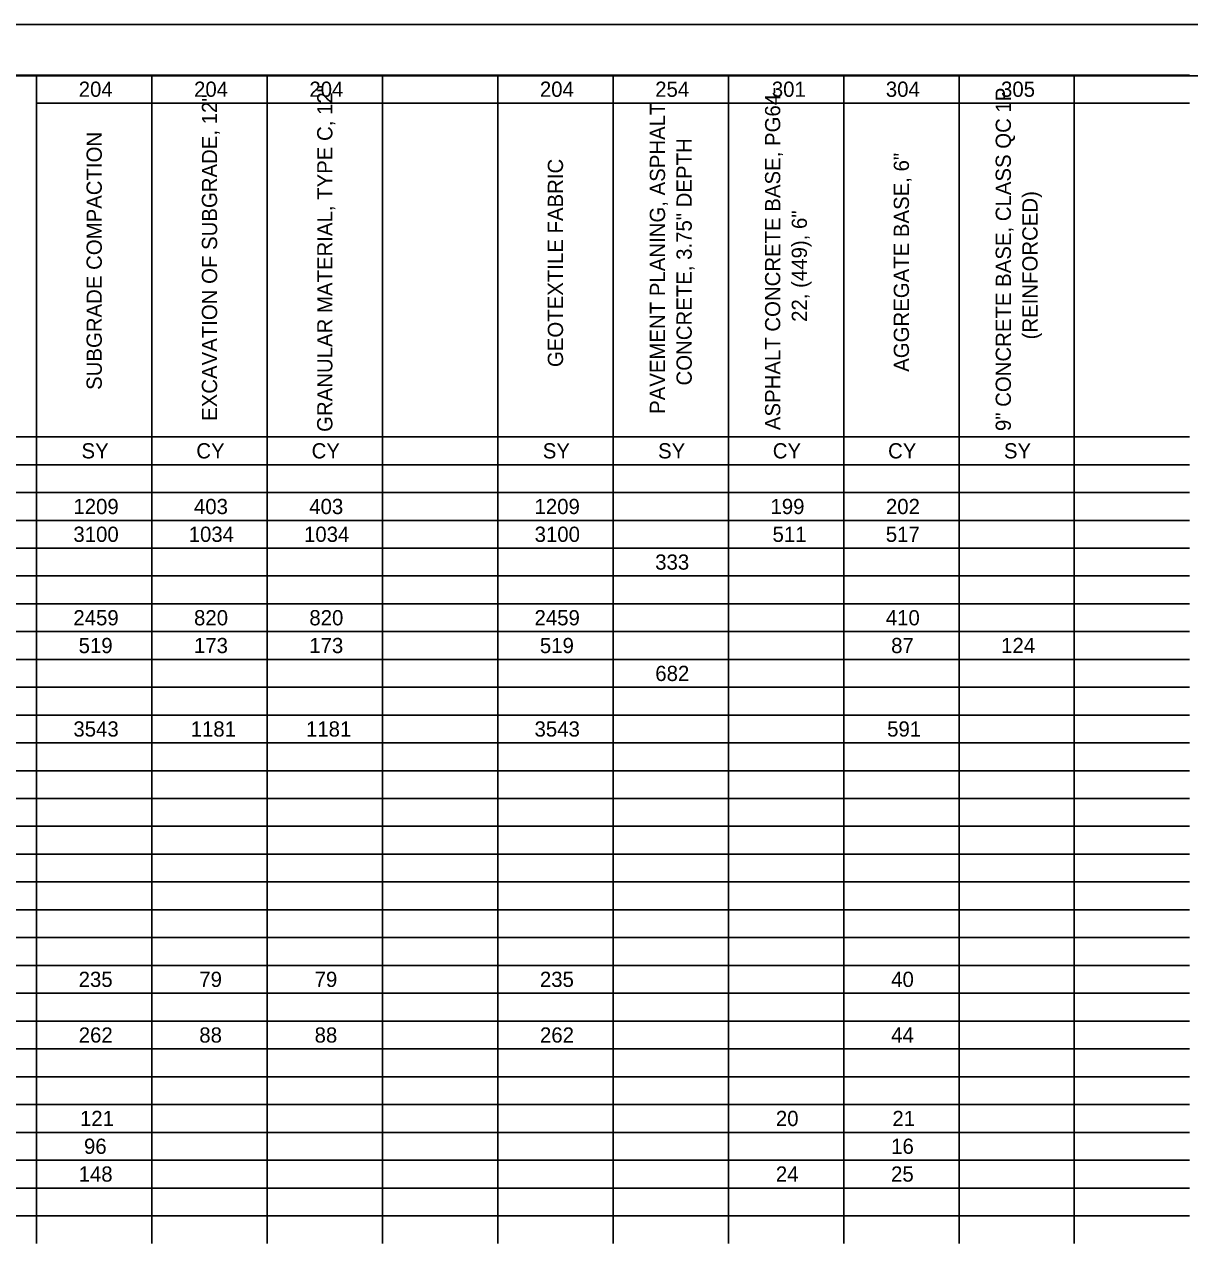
# Model space of a CAD drawing. Extents: x 0 to 34, y 0 to 22.
# Drawn here: x 11.72 to 23.04, y 10.15 to 22 of the extents above; entities that cross this region are included whole.
import ezdxf

# ---------------------------------------------------------------- set-up
doc = ezdxf.new("R2010")
doc.units = 0
for name, color, linetype in [('SH_Border', 7, 'Continuous'), ('SH_Cut_Line', 7, 'Continuous'), ('SH_Text', 7, 'Continuous')]:
    doc.layers.add(name, color=color, linetype=linetype)

msp = doc.modelspace()

# ---------------------------------------------------------------- linework, layer by layer
at = {"layer": 'SH_Border'}
msp.add_lwpolyline([(1.5, 21.5), (33.5, 21.5), (33.5, 0.5), (1.5, 0.5)], close=True, dxfattribs=at)
at = {"layer": 'SH_Cut_Line'}
msp.add_lwpolyline([(0, 0), (34, 0), (34, 22), (0, 22)], close=True, dxfattribs=at)
at = {"layer": 'SH_Text'}
for p, q in [((10.722, 21.505), (11.841, 21.505)), ((11.841, 21.505), (12.961, 21.505)), ((11.841, 21.505), (11.841, 21.235)), ((12.961, 21.505), (14.081, 21.505)), ((12.961, 21.505), (12.961, 21.235)), ((14.081, 21.505), (16.321, 21.505)), ((14.081, 21.505), (14.081, 21.235)), ((15.201, 21.505), (15.201, 21.235)), ((16.321, 21.505), (23.041, 21.505)), ((16.321, 21.505), (16.321, 21.235)), ((17.441, 21.505), (17.441, 21.235)), ((18.561, 21.505), (18.561, 21.235)), ((19.681, 21.505), (19.681, 21.235)), ((20.801, 21.505), (20.801, 21.235)), ((21.921, 21.505), (21.921, 21.235)), ((11.841, 21.235), (12.961, 21.235)), ((11.841, 21.235), (11.841, 20.965)), ((12.961, 21.235), (14.081, 21.235)), ((12.961, 21.235), (12.961, 20.965)), ((14.081, 21.235), (16.321, 21.235)), ((14.081, 21.235), (14.081, 20.965)), ((15.201, 21.235), (15.201, 20.965)), ((16.321, 21.235), (23.041, 21.235)), ((16.321, 21.235), (16.321, 20.965)), ((17.441, 21.235), (17.441, 20.965)), ((18.561, 21.235), (18.561, 20.965)), ((19.681, 21.235), (19.681, 20.965)), ((20.801, 21.235), (20.801, 20.965)), ((21.921, 21.235), (21.921, 20.965)), ((11.841, 20.965), (11.841, 20.694)), ((12.961, 20.965), (12.961, 20.694)), ((14.081, 20.965), (14.081, 20.694)), ((15.201, 20.965), (15.201, 20.694)), ((16.321, 20.965), (16.321, 20.694)), ((17.441, 20.965), (17.441, 20.694)), ((18.561, 20.965), (18.561, 20.694)), ((19.681, 20.965), (19.681, 20.694)), ((20.801, 20.965), (20.801, 20.694)), ((21.921, 20.965), (21.921, 20.694)), ((11.841, 20.694), (11.841, 20.154)), ((12.961, 20.694), (12.961, 20.154)), ((14.081, 20.694), (14.081, 20.154)), ((15.201, 20.694), (15.201, 20.154)), ((16.321, 20.694), (16.321, 20.154)), ((17.441, 20.694), (17.441, 20.154)), ((18.561, 20.694), (18.561, 20.154)), ((19.681, 20.694), (19.681, 20.154)), ((20.801, 20.694), (20.801, 20.154)), ((21.921, 20.694), (21.921, 20.154)), ((11.841, 20.154), (11.841, 19.883)), ((12.961, 20.154), (12.961, 19.883)), ((14.081, 20.154), (14.081, 19.883)), ((15.201, 20.154), (15.201, 19.883)), ((16.321, 20.154), (16.321, 19.883)), ((17.441, 20.154), (17.441, 19.883)), ((18.561, 20.154), (18.561, 19.883)), ((19.681, 20.154), (19.681, 19.883)), ((20.801, 20.154), (20.801, 19.883)), ((21.921, 20.154), (21.921, 19.883)), ((11.841, 19.883), (11.841, 19.613)), ((12.961, 19.883), (12.961, 19.613)), ((14.081, 19.883), (14.081, 19.613)), ((15.201, 19.883), (15.201, 19.613)), ((16.321, 19.883), (16.321, 19.613)), ((17.441, 19.883), (17.441, 19.613)), ((18.561, 19.883), (18.561, 19.613)), ((19.681, 19.883), (19.681, 19.613)), ((20.801, 19.883), (20.801, 19.613)), ((21.921, 19.883), (21.921, 19.613)), ((11.841, 19.613), (11.841, 19.343)), ((12.961, 19.613), (12.961, 19.343)), ((14.081, 19.613), (14.081, 19.343)), ((15.201, 19.613), (15.201, 19.343)), ((16.321, 19.613), (16.321, 19.343)), ((17.441, 19.613), (17.441, 19.343)), ((18.561, 19.613), (18.561, 19.343)), ((19.681, 19.613), (19.681, 19.343)), ((20.801, 19.613), (20.801, 19.343)), ((21.921, 19.613), (21.921, 19.343)), ((11.841, 19.343), (11.841, 19.072)), ((12.961, 19.343), (12.961, 19.072)), ((14.081, 19.343), (14.081, 19.072)), ((15.201, 19.343), (15.201, 19.072)), ((16.321, 19.343), (16.321, 19.072)), ((17.441, 19.343), (17.441, 19.072)), ((18.561, 19.343), (18.561, 19.072)), ((19.681, 19.343), (19.681, 19.072)), ((20.801, 19.343), (20.801, 19.072)), ((21.921, 19.343), (21.921, 19.072)), ((11.841, 19.072), (11.841, 18.802)), ((12.961, 19.072), (12.961, 18.802)), ((14.081, 19.072), (14.081, 18.802)), ((15.201, 19.072), (15.201, 18.802)), ((16.321, 19.072), (16.321, 18.802)), ((17.441, 19.072), (17.441, 18.802)), ((18.561, 19.072), (18.561, 18.802)), ((19.681, 19.072), (19.681, 18.802)), ((20.801, 19.072), (20.801, 18.802)), ((21.921, 19.072), (21.921, 18.802)), ((11.841, 18.802), (11.841, 18.532)), ((12.961, 18.802), (12.961, 18.532)), ((14.081, 18.802), (14.081, 18.532)), ((15.201, 18.802), (15.201, 18.532)), ((16.321, 18.802), (16.321, 18.532)), ((17.441, 18.802), (17.441, 18.532)), ((18.561, 18.802), (18.561, 18.532)), ((19.681, 18.802), (19.681, 18.532)), ((20.801, 18.802), (20.801, 18.532)), ((21.921, 18.802), (21.921, 18.532)), ((11.841, 18.532), (11.841, 18.262)), ((12.961, 18.532), (12.961, 18.262)), ((14.081, 18.532), (14.081, 18.262)), ((15.201, 18.532), (15.201, 18.262)), ((16.321, 18.532), (16.321, 18.262)), ((17.441, 18.532), (17.441, 18.262)), ((18.561, 18.532), (18.561, 18.262)), ((19.681, 18.532), (19.681, 18.262)), ((20.801, 18.532), (20.801, 18.262)), ((21.921, 18.532), (21.921, 18.262)), ((11.841, 18.262), (11.841, 17.991)), ((12.961, 18.262), (12.961, 17.991)), ((14.081, 18.262), (14.081, 17.991)), ((15.201, 18.262), (15.201, 17.991)), ((16.321, 18.262), (16.321, 17.991)), ((17.441, 18.262), (17.441, 17.991)), ((18.561, 18.262), (18.561, 17.991)), ((19.681, 18.262), (19.681, 17.991)), ((20.801, 18.262), (20.801, 17.991)), ((21.921, 18.262), (21.921, 17.991)), ((10.722, 17.991), (11.841, 17.991)), ((11.841, 17.991), (12.961, 17.991)), ((11.841, 17.991), (11.841, 17.721)), ((12.961, 17.991), (14.081, 17.991)), ((12.961, 17.991), (12.961, 17.721)), ((14.081, 17.991), (16.321, 17.991)), ((14.081, 17.991), (14.081, 17.721)), ((15.201, 17.991), (15.201, 17.721)), ((16.321, 17.991), (23.041, 17.991)), ((16.321, 17.991), (16.321, 17.721)), ((17.441, 17.991), (17.441, 17.721)), ((18.561, 17.991), (18.561, 17.721)), ((19.681, 17.991), (19.681, 17.721)), ((20.801, 17.991), (20.801, 17.721)), ((21.921, 17.991), (21.921, 17.721)), ((10.722, 17.721), (11.841, 17.721)), ((11.841, 17.721), (12.961, 17.721)), ((11.841, 17.721), (11.841, 17.451)), ((12.961, 17.721), (14.081, 17.721)), ((12.961, 17.721), (12.961, 17.451)), ((14.081, 17.721), (16.321, 17.721)), ((14.081, 17.721), (14.081, 17.451)), ((15.201, 17.721), (15.201, 17.451)), ((16.321, 17.721), (23.041, 17.721)), ((16.321, 17.721), (16.321, 17.451)), ((17.441, 17.721), (17.441, 17.451)), ((18.561, 17.721), (18.561, 17.451)), ((19.681, 17.721), (19.681, 17.451)), ((20.801, 17.721), (20.801, 17.451)), ((21.921, 17.721), (21.921, 17.451)), ((10.722, 17.451), (11.841, 17.451)), ((11.841, 17.451), (12.961, 17.451)), ((11.841, 17.451), (11.841, 17.18)), ((12.961, 17.451), (14.081, 17.451)), ((12.961, 17.451), (12.961, 17.18)), ((14.081, 17.451), (16.321, 17.451)), ((14.081, 17.451), (14.081, 17.18)), ((15.201, 17.451), (15.201, 17.18)), ((16.321, 17.451), (23.041, 17.451)), ((16.321, 17.451), (16.321, 17.18)), ((17.441, 17.451), (17.441, 17.18)), ((18.561, 17.451), (18.561, 17.18)), ((19.681, 17.451), (19.681, 17.18)), ((20.801, 17.451), (20.801, 17.18)), ((21.921, 17.451), (21.921, 17.18)), ((10.722, 17.18), (11.841, 17.18)), ((11.841, 17.18), (12.961, 17.18)), ((11.841, 17.18), (11.841, 16.91)), ((12.961, 17.18), (14.081, 17.18)), ((12.961, 17.18), (12.961, 16.91)), ((14.081, 17.18), (16.321, 17.18)), ((14.081, 17.18), (14.081, 16.91)), ((15.201, 17.18), (15.201, 16.91)), ((16.321, 17.18), (23.041, 17.18)), ((16.321, 17.18), (16.321, 16.91)), ((17.441, 17.18), (17.441, 16.91)), ((18.561, 17.18), (18.561, 16.91)), ((19.681, 17.18), (19.681, 16.91)), ((20.801, 17.18), (20.801, 16.91)), ((21.921, 17.18), (21.921, 16.91)), ((10.722, 16.91), (11.841, 16.91)), ((11.841, 16.91), (12.961, 16.91)), ((11.841, 16.91), (11.841, 16.369)), ((12.961, 16.91), (14.081, 16.91)), ((12.961, 16.91), (12.961, 16.369)), ((14.081, 16.91), (16.321, 16.91)), ((14.081, 16.91), (14.081, 16.369)), ((15.201, 16.91), (15.201, 16.369)), ((16.321, 16.91), (23.041, 16.91)), ((16.321, 16.91), (16.321, 16.369)), ((17.441, 16.91), (17.441, 16.369)), ((18.561, 16.91), (18.561, 16.369)), ((19.681, 16.91), (19.681, 16.369)), ((20.801, 16.91), (20.801, 16.369)), ((21.921, 16.91), (21.921, 16.369)), ((10.722, 16.64), (11.841, 16.64)), ((11.841, 16.64), (12.961, 16.64)), ((12.961, 16.64), (14.081, 16.64)), ((14.081, 16.64), (16.321, 16.64)), ((16.321, 16.64), (23.041, 16.64)), ((10.722, 16.369), (11.841, 16.369)), ((11.841, 16.369), (12.961, 16.369)), ((11.841, 16.369), (11.841, 16.099)), ((12.961, 16.369), (14.081, 16.369)), ((12.961, 16.369), (12.961, 16.099)), ((14.081, 16.369), (16.321, 16.369)), ((14.081, 16.369), (14.081, 16.099)), ((15.201, 16.369), (15.201, 16.099)), ((16.321, 16.369), (23.041, 16.369)), ((16.321, 16.369), (16.321, 16.099)), ((17.441, 16.369), (17.441, 16.099)), ((18.561, 16.369), (18.561, 16.099)), ((19.681, 16.369), (19.681, 16.099)), ((20.801, 16.369), (20.801, 16.099)), ((21.921, 16.369), (21.921, 16.099)), ((10.722, 16.099), (11.841, 16.099)), ((11.841, 16.099), (12.961, 16.099)), ((11.841, 16.099), (11.841, 15.829)), ((12.961, 16.099), (14.081, 16.099)), ((12.961, 16.099), (12.961, 15.829)), ((14.081, 16.099), (16.321, 16.099)), ((14.081, 16.099), (14.081, 15.829)), ((15.201, 16.099), (15.201, 15.829)), ((16.321, 16.099), (23.041, 16.099)), ((16.321, 16.099), (16.321, 15.829)), ((17.441, 16.099), (17.441, 15.829)), ((18.561, 16.099), (18.561, 15.829)), ((19.681, 16.099), (19.681, 15.829)), ((20.801, 16.099), (20.801, 15.829)), ((21.921, 16.099), (21.921, 15.829)), ((10.722, 15.829), (11.841, 15.829)), ((11.841, 15.829), (12.961, 15.829)), ((11.841, 15.829), (11.841, 15.558)), ((12.961, 15.829), (14.081, 15.829)), ((12.961, 15.829), (12.961, 15.558)), ((14.081, 15.829), (16.321, 15.829)), ((14.081, 15.829), (14.081, 15.558)), ((15.201, 15.829), (15.201, 15.558)), ((16.321, 15.829), (23.041, 15.829)), ((16.321, 15.829), (16.321, 15.558)), ((17.441, 15.829), (17.441, 15.558)), ((18.561, 15.829), (18.561, 15.558)), ((19.681, 15.829), (19.681, 15.558)), ((20.801, 15.829), (20.801, 15.558)), ((21.921, 15.829), (21.921, 15.558)), ((10.722, 15.558), (11.841, 15.558)), ((11.841, 15.558), (12.961, 15.558)), ((11.841, 15.558), (11.841, 15.018)), ((12.961, 15.558), (14.081, 15.558)), ((12.961, 15.558), (12.961, 15.018)), ((14.081, 15.558), (16.321, 15.558)), ((14.081, 15.558), (14.081, 15.018)), ((15.201, 15.558), (15.201, 15.018)), ((16.321, 15.558), (23.041, 15.558)), ((16.321, 15.558), (16.321, 15.018)), ((17.441, 15.558), (17.441, 15.018)), ((18.561, 15.558), (18.561, 15.018)), ((19.681, 15.558), (19.681, 15.018)), ((20.801, 15.558), (20.801, 15.018)), ((21.921, 15.558), (21.921, 15.018)), ((10.722, 15.288), (11.841, 15.288)), ((11.841, 15.288), (12.961, 15.288)), ((12.961, 15.288), (14.081, 15.288)), ((14.081, 15.288), (16.321, 15.288)), ((16.321, 15.288), (23.041, 15.288)), ((10.722, 15.018), (11.841, 15.018)), ((11.841, 15.018), (12.961, 15.018)), ((11.841, 15.018), (11.841, 14.747)), ((12.961, 15.018), (14.081, 15.018)), ((12.961, 15.018), (12.961, 14.747)), ((14.081, 15.018), (16.321, 15.018)), ((14.081, 15.018), (14.081, 14.747)), ((15.201, 15.018), (15.201, 14.747)), ((16.321, 15.018), (23.041, 15.018)), ((16.321, 15.018), (16.321, 14.747)), ((17.441, 15.018), (17.441, 14.747)), ((18.561, 15.018), (18.561, 14.747)), ((19.681, 15.018), (19.681, 14.747)), ((20.801, 15.018), (20.801, 14.747)), ((21.921, 15.018), (21.921, 14.747)), ((10.722, 14.747), (11.841, 14.747)), ((11.841, 14.747), (12.961, 14.747)), ((11.841, 14.747), (11.841, 14.477)), ((12.961, 14.747), (14.081, 14.747)), ((12.961, 14.747), (12.961, 14.477)), ((14.081, 14.747), (16.321, 14.747)), ((14.081, 14.747), (14.081, 14.477)), ((15.201, 14.747), (15.201, 14.477)), ((16.321, 14.747), (23.041, 14.747)), ((16.321, 14.747), (16.321, 14.477)), ((17.441, 14.747), (17.441, 14.477)), ((18.561, 14.747), (18.561, 14.477)), ((19.681, 14.747), (19.681, 14.477)), ((20.801, 14.747), (20.801, 14.477)), ((21.921, 14.747), (21.921, 14.477)), ((10.722, 14.477), (11.841, 14.477)), ((11.841, 14.477), (12.961, 14.477)), ((11.841, 14.477), (11.841, 14.207)), ((12.961, 14.477), (14.081, 14.477)), ((12.961, 14.477), (12.961, 14.207)), ((14.081, 14.477), (16.321, 14.477)), ((14.081, 14.477), (14.081, 14.207)), ((15.201, 14.477), (15.201, 14.207)), ((16.321, 14.477), (23.041, 14.477)), ((16.321, 14.477), (16.321, 14.207)), ((17.441, 14.477), (17.441, 14.207)), ((18.561, 14.477), (18.561, 14.207)), ((19.681, 14.477), (19.681, 14.207)), ((20.801, 14.477), (20.801, 14.207)), ((21.921, 14.477), (21.921, 14.207)), ((10.722, 14.207), (11.841, 14.207)), ((11.841, 14.207), (12.961, 14.207)), ((11.841, 14.207), (11.841, 13.396)), ((12.961, 14.207), (14.081, 14.207)), ((12.961, 14.207), (12.961, 13.396)), ((14.081, 14.207), (16.321, 14.207)), ((14.081, 14.207), (14.081, 13.396)), ((15.201, 14.207), (15.201, 13.396)), ((16.321, 14.207), (23.041, 14.207)), ((16.321, 14.207), (16.321, 13.396)), ((17.441, 14.207), (17.441, 13.396)), ((18.561, 14.207), (18.561, 13.396)), ((19.681, 14.207), (19.681, 13.396)), ((20.801, 14.207), (20.801, 13.396)), ((21.921, 14.207), (21.921, 13.396)), ((10.722, 13.936), (11.841, 13.936)), ((11.841, 13.936), (12.961, 13.936)), ((12.961, 13.936), (14.081, 13.936)), ((14.081, 13.936), (16.321, 13.936)), ((16.321, 13.936), (23.041, 13.936)), ((10.722, 13.666), (11.841, 13.666)), ((11.841, 13.666), (12.961, 13.666)), ((12.961, 13.666), (14.081, 13.666)), ((14.081, 13.666), (16.321, 13.666)), ((16.321, 13.666), (23.041, 13.666)), ((10.722, 13.396), (11.841, 13.396)), ((11.841, 13.396), (12.961, 13.396)), ((11.841, 13.396), (11.841, 13.125)), ((12.961, 13.396), (14.081, 13.396)), ((12.961, 13.396), (12.961, 13.125)), ((14.081, 13.396), (16.321, 13.396)), ((14.081, 13.396), (14.081, 13.125)), ((15.201, 13.396), (15.201, 13.125)), ((16.321, 13.396), (23.041, 13.396)), ((16.321, 13.396), (16.321, 13.125)), ((17.441, 13.396), (17.441, 13.125)), ((18.561, 13.396), (18.561, 13.125)), ((19.681, 13.396), (19.681, 13.125)), ((20.801, 13.396), (20.801, 13.125)), ((21.921, 13.396), (21.921, 13.125)), ((10.722, 13.125), (11.841, 13.125)), ((11.841, 13.125), (12.961, 13.125)), ((11.841, 13.125), (11.841, 12.044)), ((12.961, 13.125), (14.081, 13.125)), ((12.961, 13.125), (12.961, 12.044)), ((14.081, 13.125), (16.321, 13.125)), ((14.081, 13.125), (14.081, 12.044)), ((15.201, 13.125), (15.201, 12.044)), ((16.321, 13.125), (23.041, 13.125)), ((16.321, 13.125), (16.321, 12.044)), ((17.441, 13.125), (17.441, 12.044)), ((18.561, 13.125), (18.561, 12.044)), ((19.681, 13.125), (19.681, 12.044)), ((20.801, 13.125), (20.801, 12.044)), ((21.921, 13.125), (21.921, 12.044)), ((10.722, 12.855), (11.841, 12.855)), ((11.841, 12.855), (12.961, 12.855)), ((12.961, 12.855), (14.081, 12.855)), ((14.081, 12.855), (16.321, 12.855)), ((16.321, 12.855), (23.041, 12.855)), ((10.722, 12.585), (11.841, 12.585)), ((11.841, 12.585), (12.961, 12.585)), ((12.961, 12.585), (14.081, 12.585)), ((14.081, 12.585), (16.321, 12.585)), ((16.321, 12.585), (23.041, 12.585)), ((10.722, 12.314), (11.841, 12.314)), ((11.841, 12.314), (12.961, 12.314)), ((12.961, 12.314), (14.081, 12.314)), ((14.081, 12.314), (16.321, 12.314)), ((16.321, 12.314), (23.041, 12.314)), ((10.722, 12.044), (11.841, 12.044)), ((11.841, 12.044), (12.961, 12.044)), ((11.841, 12.044), (11.841, 11.774)), ((12.961, 12.044), (14.081, 12.044)), ((12.961, 12.044), (12.961, 11.774)), ((14.081, 12.044), (16.321, 12.044)), ((14.081, 12.044), (14.081, 11.774)), ((15.201, 12.044), (15.201, 11.774)), ((16.321, 12.044), (23.041, 12.044)), ((16.321, 12.044), (16.321, 11.774)), ((17.441, 12.044), (17.441, 11.774)), ((18.561, 12.044), (18.561, 11.774)), ((19.681, 12.044), (19.681, 11.774)), ((20.801, 12.044), (20.801, 11.774)), ((21.921, 12.044), (21.921, 11.774)), ((10.722, 11.774), (11.841, 11.774)), ((11.841, 11.774), (12.961, 11.774)), ((11.841, 11.774), (11.841, 10.692)), ((12.961, 11.774), (14.081, 11.774)), ((12.961, 11.774), (12.961, 10.692)), ((14.081, 11.774), (16.321, 11.774)), ((14.081, 11.774), (14.081, 10.692)), ((15.201, 11.774), (15.201, 10.692)), ((16.321, 11.774), (23.041, 11.774)), ((16.321, 11.774), (16.321, 10.692)), ((17.441, 11.774), (17.441, 10.692)), ((18.561, 11.774), (18.561, 10.692)), ((19.681, 11.774), (19.681, 10.692)), ((20.801, 11.774), (20.801, 10.692)), ((21.921, 11.774), (21.921, 10.692)), ((10.722, 11.503), (11.841, 11.503)), ((11.841, 11.503), (12.961, 11.503)), ((12.961, 11.503), (14.081, 11.503)), ((14.081, 11.503), (16.321, 11.503)), ((16.321, 11.503), (23.041, 11.503)), ((10.722, 11.233), (11.841, 11.233)), ((11.841, 11.233), (12.961, 11.233)), ((12.961, 11.233), (14.081, 11.233)), ((14.081, 11.233), (16.321, 11.233)), ((16.321, 11.233), (23.041, 11.233)), ((10.722, 10.963), (11.841, 10.963)), ((11.841, 10.963), (12.961, 10.963)), ((12.961, 10.963), (14.081, 10.963)), ((14.081, 10.963), (16.321, 10.963)), ((16.321, 10.963), (23.041, 10.963)), ((10.722, 10.692), (11.841, 10.692)), ((11.841, 10.692), (12.961, 10.692)), ((11.841, 10.692), (11.841, 10.152)), ((12.961, 10.692), (14.081, 10.692)), ((12.961, 10.692), (12.961, 10.152)), ((14.081, 10.692), (16.321, 10.692)), ((14.081, 10.692), (14.081, 10.152)), ((15.201, 10.692), (15.201, 10.152)), ((16.321, 10.692), (23.041, 10.692)), ((16.321, 10.692), (16.321, 10.152)), ((17.441, 10.692), (17.441, 10.152)), ((18.561, 10.692), (18.561, 10.152)), ((19.681, 10.692), (19.681, 10.152)), ((20.801, 10.692), (20.801, 10.152)), ((21.921, 10.692), (21.921, 10.152)), ((10.722, 10.422), (11.841, 10.422)), ((11.841, 10.422), (12.961, 10.422)), ((12.961, 10.422), (14.081, 10.422)), ((14.081, 10.422), (16.321, 10.422)), ((16.321, 10.422), (23.041, 10.422))]:
    msp.add_line(p, q, dxfattribs=at)

# ---------------------------------------------------------------- texts
for s, p in [('204', (12.251, 21.296)), ('204', (13.371, 21.296)), ('204', (14.491, 21.296)), ('204', (16.73, 21.296)), ('254', (17.85, 21.296)), ('301', (18.983, 21.296)), ('304', (20.09, 21.296)), ('305', (21.209, 21.296)), ('SY', (12.278, 17.782)), ('CY', (13.393, 17.782)), ('CY', (14.513, 17.782)), ('SY', (16.758, 17.782)), ('SY', (17.878, 17.782)), ('CY', (18.992, 17.782)), ('CY', (20.112, 17.782)), ('SY', (21.237, 17.782)), ('1209', (12.199, 17.241)), ('403', (13.37, 17.241)), ('403', (14.49, 17.241)), ('1209', (16.678, 17.241)), ('199', (18.97, 17.241)), ('202', (20.091, 17.241)), ('3100', (12.199, 16.971)), ('1034', (13.319, 16.971)), ('1034', (14.439, 16.971)), ('3100', (16.679, 16.971)), ('511', (18.99, 16.971)), ('517', (20.09, 16.971)), ('333', (17.85, 16.701)), ('2459', (12.199, 16.16)), ('820', (13.371, 16.16)), ('820', (14.491, 16.16)), ('2459', (16.678, 16.16)), ('410', (20.09, 16.16)), ('519', (12.25, 15.89)), ('173', (13.37, 15.89)), ('173', (14.49, 15.89)), ('519', (16.73, 15.89)), ('87', (20.142, 15.89)), ('124', (21.21, 15.89)), ('682', (17.851, 15.619)), ('3543', (12.199, 15.079)), ('1181', (13.338, 15.079)), ('1181', (14.458, 15.079)), ('3543', (16.678, 15.079)), ('591', (20.103, 15.079)), ('235', (12.25, 12.646)), ('79', (13.422, 12.646)), ('79', (14.542, 12.646)), ('235', (16.73, 12.646)), ('40', (20.142, 12.646)), ('262', (12.251, 12.105)), ('88', (13.422, 12.105)), ('88', (14.542, 12.105)), ('262', (16.731, 12.105)), ('44', (20.142, 12.105)), ('121', (12.263, 11.294)), ('20', (19.022, 11.294)), ('21', (20.154, 11.294)), ('96', (12.302, 11.024)), ('16', (20.142, 11.024)), ('148', (12.25, 10.754)), ('24', (19.022, 10.754)), ('25', (20.141, 10.754))]:
    msp.add_text(s, height=0.148, dxfattribs=at).set_placement(p)
for s, p in [('GRANULAR MATERIAL, TYPE C, 12"', (14.715, 18.04)), ('ASPHALT CONCRETE BASE, PG64-', (19.065, 18.057)), ('9" CONCRETE BASE, CLASS QC 1P ', (21.305, 18.048)), ('EXCAVATION OF SUBGRADE, 12"', (13.595, 18.147)), ('PAVEMENT PLANING, ASPHALT ', (17.946, 18.215)), ('SUBGRADE COMPACTION', (12.475, 18.448)), ('CONCRETE, 3.75" DEPTH', (18.205, 18.491)), ('AGGREGATE BASE, 6"', (20.315, 18.624)), ('GEOTEXTILE FABRIC', (16.955, 18.67)), ('(REINFORCED)', (21.564, 18.939)), ('22, (449), 6"', (19.324, 19.109))]:
    msp.add_text(s, height=0.14804, rotation=90, dxfattribs=at).set_placement(p)

doc.saveas('drawing.dxf')
